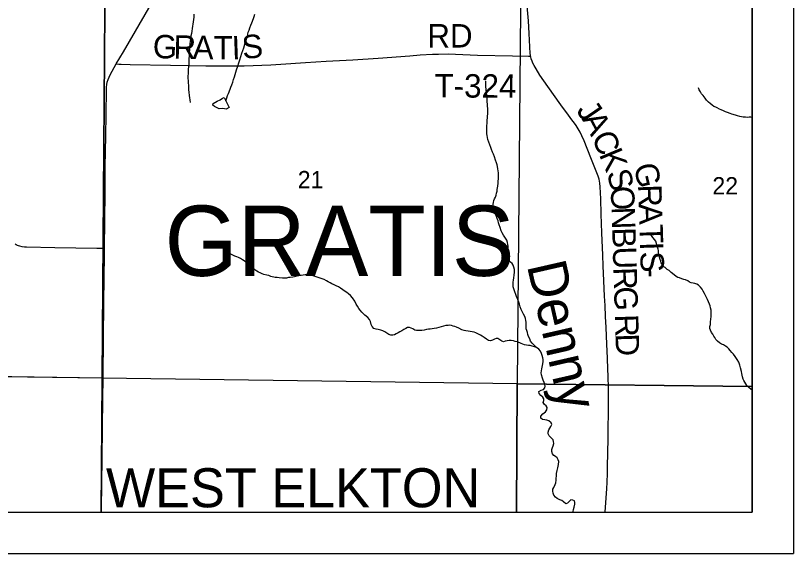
# Model space of a CAD drawing. Extents: x -8.8 to 41.4, y 0 to 34.6.
# Drawn here: x -3.661 to -1.774, y 14 to 15.304 of the extents above; entities that cross this region are included whole.
import ezdxf

# ---------------------------------------------------------------- set-up
doc = ezdxf.new("R2010")
doc.units = 0
for name, color, linetype in [('GM_X_Corporation', 7, 'Continuous'), ('GM_X_County_Road', 7, 'Continuous'), ('GM_X_Minor_River', 7, 'Continuous'), ('GM_X_Minor_River_Text', 7, 'Continuous'), ('GM_X_Section_Text', 7, 'Continuous'), ('GM_X_State_Location', 7, 'Continuous'), ('GM_X_State_Route', 7, 'Continuous'), ('GM_X_Township_Road', 7, 'Continuous'), ('GM_X_Township_Text', 7, 'Continuous'), ('GM_X_Unincorporated', 7, 'Continuous'), ('SH_Border', 7, 'Continuous')]:
    doc.layers.add(name, color=color, linetype=linetype)

msp = doc.modelspace()

# ---------------------------------------------------------------- linework, layer by layer
at = {"layer": 'GM_X_Corporation'}
msp.add_lwpolyline([(-5.4008, 18.6369), (-5.4129, 17.3836), (-5.4212, 16.5483), (-5.4282, 16.3507), (-5.435, 15.3164), (-5.4368, 15.0446), (-5.4404, 14.5882), (-5.4429, 14.2618), (-5.4432, 14.2265), (-5.4442, 14.1), (-1.8743, 14.1), (-1.8743, 18.5906)], dxfattribs=at)
for points in [[(-4.4369, 15.4422), (-3.4436, 15.4293), (-3.4507, 14.4245), (-4.4383, 14.4395)], [(-3.4436, 15.4293), (-2.4357, 15.4097), (-2.4445, 14.411), (-3.4507, 14.4245)], [(-1.8743, 14.4042), (-1.8743, 15.4006), (-2.4357, 15.4097), (-2.4445, 14.411)], [(-4.443, 14.1), (-3.4536, 14.1), (-3.4507, 14.4245), (-4.4383, 14.4395)], [(-3.9447, 14.1), (-3.4526, 14.1), (-3.4525, 14.1076), (-3.4509, 14.2324), (-3.4492, 14.3764), (-3.4488, 14.4247), (-3.938, 14.4315)], [(-3.4536, 14.1), (-2.4463, 14.1), (-2.4445, 14.411), (-3.4507, 14.4245)], [(-2.4463, 14.1), (-1.8743, 14.1), (-1.8743, 14.4042), (-2.4445, 14.411)]]:
    msp.add_lwpolyline(points, close=True, dxfattribs=at)
at = {"layer": 'GM_X_County_Road'}
msp.add_lwpolyline([(-3.4451, 14.7387), (-3.451, 14.7389), (-3.4641, 14.7393), (-3.5659, 14.741), (-3.6342, 14.742), (-3.6392, 14.7423), (-3.6446, 14.7431), (-3.6501, 14.7445), (-3.6535, 14.7456), (-3.6563, 14.7466), (-3.6592, 14.7478), (-3.6618, 14.7492)], dxfattribs=at)
at = {"layer": 'GM_X_Minor_River'}
for points in [[(-3.2282, 15.3068), (-3.2288, 15.3), (-3.2293, 15.294), (-3.2299, 15.2887), (-3.2312, 15.2826), (-3.2317, 15.2777), (-3.2326, 15.272), (-3.2336, 15.2656), (-3.2345, 15.2599), (-3.2354, 15.2542), (-3.2368, 15.2463), (-3.2373, 15.2414), (-3.2382, 15.2349), (-3.2388, 15.2266), (-3.239, 15.2201), (-3.2396, 15.2148), (-3.2403, 15.1901), (-3.2408, 15.1852), (-3.2419, 15.1739), (-3.242, 15.1685), (-3.2422, 15.1632), (-3.2427, 15.1568), (-3.2429, 15.1515), (-3.2426, 15.1461), (-3.2424, 15.14), (-3.2418, 15.1347), (-3.2414, 15.1233), (-3.2408, 15.1183), (-3.2395, 15.1103), (-3.2389, 15.1046), (-3.2383, 15.0997), (-3.2377, 15.0932)], [(-3.1509, 15.0974), (-3.1504, 15.0991), (-3.1487, 15.1043), (-3.1466, 15.1103), (-3.1446, 15.1145), (-3.1405, 15.125), (-3.1388, 15.1299), (-3.1367, 15.1359), (-3.1342, 15.1426), (-3.1322, 15.149), (-3.1297, 15.1554), (-3.125, 15.172), (-3.1221, 15.1814), (-3.1192, 15.1893), (-3.1167, 15.1968), (-3.1146, 15.2043), (-3.112, 15.2122), (-3.1095, 15.2194), (-3.1071, 15.2258), (-3.1037, 15.2378), (-3.1016, 15.2442), (-3.1003, 15.2495), (-3.0986, 15.254), (-3.0977, 15.2585), (-3.0965, 15.2634), (-3.0944, 15.2687), (-3.0927, 15.2743), (-3.0906, 15.2803), (-3.0882, 15.286), (-3.0841, 15.2965), (-3.0824, 15.3014), (-3.0803, 15.307)], [(-2.4667, 14.749), (-2.4677, 14.7536), (-2.4697, 14.759), (-2.4743, 14.7663), (-2.4775, 14.7717), (-2.4811, 14.7772), (-2.4832, 14.7822), (-2.4859, 14.7898), (-2.4879, 14.7964), (-2.4893, 14.801), (-2.4902, 14.8059), (-2.4926, 14.8121), (-2.4943, 14.8163), (-2.4975, 14.8236), (-2.4995, 14.829), (-2.5012, 14.8352), (-2.5025, 14.8413), (-2.5023, 14.8462), (-2.5018, 14.8504), (-2.5008, 14.8553), (-2.4992, 14.8594), (-2.4972, 14.8636), (-2.4955, 14.8681), (-2.4942, 14.8734), (-2.4932, 14.8783), (-2.4927, 14.8825), (-2.4913, 14.8904), (-2.4907, 14.8976), (-2.4901, 14.9025), (-2.4895, 14.9082), (-2.4894, 14.9132), (-2.4896, 14.9181), (-2.4898, 14.9223), (-2.4903, 14.9276), (-2.4909, 14.9318), (-2.4922, 14.9376), (-2.4928, 14.9418), (-2.4945, 14.9468), (-2.497, 14.9529), (-2.4993, 14.961), (-2.5017, 14.9675), (-2.5038, 14.9729), (-2.5062, 14.9794), (-2.5083, 14.9837), (-2.513, 14.9968), (-2.5151, 15.0029), (-2.5164, 15.0079), (-2.517, 15.0132), (-2.5176, 15.0174), (-2.5177, 15.0235), (-2.5176, 15.0281), (-2.5177, 15.0334), (-2.5173, 15.0459), (-2.5168, 15.0505), (-2.5162, 15.0558), (-2.516, 15.0604), (-2.5155, 15.0645), (-2.5151, 15.0748), (-2.5154, 15.079), (-2.5159, 15.0835), (-2.5165, 15.0893), (-2.5167, 15.0946), (-2.5174, 15.1072), (-2.5183, 15.1118), (-2.5185, 15.116), (-2.5197, 15.1259), (-2.5203, 15.1305), (-2.5205, 15.1354), (-2.5201, 15.1449)], [(-1.8743, 15.0568), (-1.8774, 15.0572), (-1.8815, 15.0573), (-1.8856, 15.057), (-1.8905, 15.0572), (-1.8961, 15.0577), (-1.9006, 15.0582), (-1.9047, 15.0591), (-1.9096, 15.0608), (-1.9148, 15.0621), (-1.9237, 15.0646), (-1.9278, 15.0662), (-1.9341, 15.0687), (-1.9393, 15.0707), (-1.9437, 15.0728), (-1.9496, 15.0752), (-1.9537, 15.0769), (-1.9589, 15.0797), (-1.9629, 15.0817), (-1.967, 15.0833), (-1.9718, 15.0865), (-1.9765, 15.0905), (-1.9805, 15.094), (-1.9849, 15.0987), (-1.9881, 15.1033), (-1.9931, 15.1096), (-1.9975, 15.1139), (-1.9999, 15.1185), (-2.0031, 15.1235), (-2.0048, 15.1285)], [(-3.1509, 15.0974), (-3.1428, 15.081), (-3.1501, 15.0771), (-3.158, 15.0784), (-3.1672, 15.0779), (-3.1739, 15.0812), (-3.1787, 15.0836), (-3.1825, 15.0864), (-3.1816, 15.0905), (-3.1723, 15.096), (-3.1646, 15.0991), (-3.1588, 15.1035)], [(-3.1588, 15.1035), (-3.1551, 15.1054)], [(-3.1551, 15.1054), (-3.1509, 15.0974)], [(-2.1004, 14.7248), (-2.1014, 14.7298), (-2.1017, 14.734), (-2.1027, 14.7378), (-2.1055, 14.747), (-2.1065, 14.7516), (-2.1082, 14.7566), (-2.1141, 14.7651), (-2.1177, 14.769), (-2.1214, 14.7733)], [(-2.3568, 14.2609), (-2.3555, 14.2666), (-2.3561, 14.2712), (-2.3574, 14.2754), (-2.3625, 14.2808), (-2.3668, 14.2852), (-2.3693, 14.2898), (-2.3695, 14.294), (-2.3678, 14.2993), (-2.3651, 14.3034), (-2.3626, 14.3079), (-2.3602, 14.3127), (-2.3616, 14.3169), (-2.3674, 14.3217), (-2.3722, 14.3233), (-2.3775, 14.3239), (-2.3827, 14.3248), (-2.3867, 14.3279), (-2.3873, 14.3325), (-2.3818, 14.3384), (-2.376, 14.3432), (-2.3721, 14.3481), (-2.3715, 14.3534), (-2.374, 14.358), (-2.3784, 14.3612), (-2.3809, 14.3658), (-2.3799, 14.3703), (-2.3794, 14.3745), (-2.3819, 14.3791), (-2.387, 14.3827), (-2.3906, 14.3878), (-2.3915, 14.3927), (-2.3858, 14.396), (-2.3805, 14.397), (-2.3773, 14.4011), (-2.3768, 14.4056), (-2.3774, 14.4098), (-2.3787, 14.414), (-2.3815, 14.4198), (-2.3832, 14.4248), (-2.3852, 14.4329), (-2.3858, 14.4375), (-2.3856, 14.4424), (-2.3847, 14.4473), (-2.3829, 14.4552), (-2.382, 14.4594), (-2.3814, 14.4651), (-2.3816, 14.47), (-2.3822, 14.4742), (-2.3835, 14.4796), (-2.3856, 14.4846), (-2.388, 14.49), (-2.392, 14.4947), (-2.3971, 14.4994), (-2.4029, 14.5049), (-2.4076, 14.5096), (-2.412, 14.5147), (-2.414, 14.52), (-2.4165, 14.5254), (-2.4182, 14.5304), (-2.4195, 14.5354), (-2.4208, 14.54), (-2.4225, 14.5446), (-2.4228, 14.5492), (-2.4229, 14.5545), (-2.4227, 14.5606), (-2.4233, 14.5648), (-2.4243, 14.5694), (-2.426, 14.574), (-2.4288, 14.5798), (-2.432, 14.586), (-2.4348, 14.5914), (-2.4368, 14.5975), (-2.4388, 14.6044), (-2.4405, 14.6094), (-2.4429, 14.6152), (-2.445, 14.6202), (-2.4477, 14.6279), (-2.4498, 14.634), (-2.4521, 14.6417), (-2.4539, 14.6459), (-2.4544, 14.6509), (-2.4542, 14.6577), (-2.4533, 14.6623), (-2.4523, 14.6676), (-2.4513, 14.6744), (-2.4511, 14.6816), (-2.4512, 14.6884), (-2.4521, 14.6938), (-2.4539, 14.6984), (-2.4567, 14.7027), (-2.4607, 14.7062), (-2.4651, 14.7105), (-2.4675, 14.7159), (-2.4688, 14.7205), (-2.4694, 14.7247), (-2.4689, 14.73), (-2.4672, 14.7353), (-2.4663, 14.7398), (-2.4661, 14.7448), (-2.4667, 14.749)], [(-2.8936, 14.6536), (-2.8976, 14.656), (-2.9024, 14.6581), (-2.9065, 14.6605), (-2.9124, 14.6637), (-2.922, 14.667), (-2.9295, 14.6695), (-2.9339, 14.6712), (-2.9391, 14.6728), (-2.9443, 14.6741), (-2.9488, 14.6746), (-2.9537, 14.6752), (-2.9586, 14.6749), (-2.9631, 14.6743), (-2.968, 14.6737), (-2.9737, 14.6727), (-2.9782, 14.6721), (-2.9846, 14.6707), (-2.9888, 14.6697), (-2.9949, 14.6691), (-2.999, 14.6685), (-3.0039, 14.6675), (-3.0092, 14.6672), (-3.0133, 14.6674), (-3.0219, 14.668), (-3.0264, 14.6685), (-3.0313, 14.669), (-3.0417, 14.6716), (-3.0469, 14.6737), (-3.0518, 14.6746), (-3.0585, 14.6763), (-3.0626, 14.6775), (-3.0677, 14.68), (-3.0718, 14.6816), (-3.0758, 14.6844), (-3.0802, 14.6876), (-3.0846, 14.6903), (-3.0894, 14.6943), (-3.0974, 14.7014), (-3.1021, 14.7057), (-3.1065, 14.7092), (-3.1105, 14.712), (-3.115, 14.7148), (-3.1198, 14.7172), (-3.1242, 14.7189), (-3.129, 14.7209), (-3.1342, 14.7233), (-3.1386, 14.7254), (-3.1435, 14.7266)], [(-1.8743, 14.3956), (-1.8775, 14.3978), (-1.8827, 14.4022), (-1.8871, 14.4069), (-1.8896, 14.4111), (-1.8922, 14.415), (-1.8943, 14.4188), (-1.8961, 14.4227), (-1.8979, 14.4284), (-1.8992, 14.4361), (-1.9005, 14.4407), (-1.9026, 14.4498), (-1.9043, 14.4564), (-1.9071, 14.4633), (-1.9107, 14.4702), (-1.9158, 14.4776), (-1.9195, 14.4826), (-1.9239, 14.4869), (-1.9276, 14.4916), (-1.9309, 14.4955), (-1.9353, 14.4998), (-1.939, 14.5026), (-1.9439, 14.5054), (-1.9491, 14.5074), (-1.954, 14.5106), (-1.9588, 14.5145), (-1.9624, 14.5188), (-1.965, 14.523), (-1.9675, 14.5269), (-1.9697, 14.5315), (-1.973, 14.5358), (-1.9755, 14.5408), (-1.9769, 14.5454), (-1.9767, 14.55), (-1.9758, 14.5549), (-1.9753, 14.5617), (-1.9747, 14.5678), (-1.9741, 14.5746), (-1.9737, 14.5894), (-1.9751, 14.5952), (-1.9761, 14.6001), (-1.9779, 14.604), (-1.9803, 14.6101), (-1.9825, 14.6151), (-1.9843, 14.619), (-1.9879, 14.6255), (-1.99, 14.6302), (-1.9929, 14.6359), (-1.9958, 14.6406), (-1.9998, 14.6452), (-2.0043, 14.6499), (-2.0087, 14.6527), (-2.0132, 14.6544), (-2.0178, 14.6549), (-2.0223, 14.6558), (-2.0264, 14.6578), (-2.0305, 14.6605), (-2.0358, 14.663), (-2.0403, 14.6642), (-2.0452, 14.6655), (-2.0504, 14.6676), (-2.0549, 14.6688), (-2.0587, 14.6712), (-2.0639, 14.6752), (-2.0709, 14.6811), (-2.0761, 14.6854), (-2.0809, 14.6882), (-2.0857, 14.6933), (-2.0899, 14.6953), (-2.0916, 14.6991), (-2.0953, 14.7042), (-2.0963, 14.7084), (-2.0977, 14.7126), (-2.0997, 14.721), (-2.1004, 14.7248)], [(-2.3971, 14.4994), (-2.4127, 14.504), (-2.4172, 14.5038), (-2.4217, 14.5047), (-2.4262, 14.5059), (-2.4306, 14.5076), (-2.4347, 14.5092), (-2.4436, 14.5125), (-2.4488, 14.5138), (-2.4529, 14.5151), (-2.4585, 14.516), (-2.4634, 14.5161), (-2.4683, 14.5155), (-2.4732, 14.5141), (-2.4778, 14.5131), (-2.4819, 14.5144), (-2.4863, 14.5175), (-2.491, 14.5207), (-2.4955, 14.5209), (-2.4997, 14.5195), (-2.5043, 14.5173), (-2.5093, 14.5155), (-2.5137, 14.5164), (-2.5189, 14.5196), (-2.5247, 14.5236), (-2.5291, 14.5268), (-2.5336, 14.5288), (-2.5395, 14.5324), (-2.5443, 14.5348), (-2.5483, 14.5361), (-2.5536, 14.5374), (-2.558, 14.5383), (-2.5629, 14.5384), (-2.5685, 14.5393), (-2.5726, 14.5402), (-2.5786, 14.5423), (-2.5856, 14.5459), (-2.5911, 14.5483), (-2.5952, 14.55), (-2.5997, 14.5512), (-2.6037, 14.5525), (-2.6079, 14.553), (-2.612, 14.5527), (-2.6173, 14.5521), (-2.623, 14.5508), (-2.629, 14.549), (-2.6347, 14.5477), (-2.64, 14.5463), (-2.6457, 14.545), (-2.6552, 14.5437), (-2.6597, 14.5435), (-2.6646, 14.5428), (-2.6699, 14.5415), (-2.6759, 14.5405), (-2.6808, 14.5403), (-2.6884, 14.5401), (-2.6928, 14.5414), (-2.6976, 14.5442), (-2.7017, 14.5462), (-2.7057, 14.5478), (-2.7103, 14.5476), (-2.7145, 14.545), (-2.7195, 14.5425), (-2.7244, 14.5396), (-2.7287, 14.5371), (-2.7329, 14.5349), (-2.7375, 14.532), (-2.7417, 14.5302), (-2.7462, 14.5292), (-2.7507, 14.5294), (-2.7556, 14.5306), (-2.7603, 14.5338), (-2.7655, 14.5374), (-2.7703, 14.5398), (-2.7751, 14.5411), (-2.7818, 14.5428), (-2.7863, 14.5437), (-2.7919, 14.545), (-2.7962, 14.5501), (-2.7987, 14.5551), (-2.8003, 14.562), (-2.8024, 14.567), (-2.8067, 14.572), (-2.814, 14.5776), (-2.8213, 14.5846), (-2.8249, 14.5897), (-2.8285, 14.594), (-2.8313, 14.599), (-2.8348, 14.6044), (-2.838, 14.6114), (-2.8437, 14.6199), (-2.8488, 14.6254), (-2.8531, 14.6293), (-2.8575, 14.6328), (-2.8615, 14.6352), (-2.8671, 14.6388), (-2.8725, 14.6432), (-2.8777, 14.646), (-2.8832, 14.6484), (-2.8884, 14.6508), (-2.8936, 14.6536)], [(-2.3086, 14.1), (-2.3084, 14.1013), (-2.3075, 14.1062), (-2.3061, 14.1123), (-2.3048, 14.1191), (-2.3042, 14.1236), (-2.3052, 14.1278), (-2.3097, 14.1291), (-2.3138, 14.13), (-2.3184, 14.1259), (-2.322, 14.1215), (-2.3262, 14.1201), (-2.3316, 14.1252), (-2.336, 14.1279), (-2.3412, 14.1296), (-2.3471, 14.1328), (-2.3511, 14.136), (-2.3551, 14.1414), (-2.3568, 14.1457), (-2.3581, 14.1506), (-2.3576, 14.1556), (-2.3555, 14.1597), (-2.3523, 14.1668), (-2.3506, 14.1713), (-2.3497, 14.1774), (-2.3495, 14.1816), (-2.3493, 14.188), (-2.3487, 14.1941), (-2.3473, 14.2009), (-2.3459, 14.2073), (-2.3441, 14.2157), (-2.3435, 14.2225), (-2.3445, 14.2271), (-2.347, 14.2313), (-2.351, 14.2353), (-2.3558, 14.2373), (-2.359, 14.2416), (-2.3603, 14.2469), (-2.3601, 14.2515), (-2.3585, 14.2568), (-2.3568, 14.2609)]]:
    msp.add_lwpolyline(points, dxfattribs=at)
at = {"layer": 'GM_X_State_Route'}
msp.add_line((-3.4486, 14.4242), (-3.4485, 14.4302), dxfattribs=at)
for points in [[(-3.4485, 14.4302), (-3.4464, 14.6094), (-3.4452, 14.7243), (-3.4451, 14.7387), (-3.4439, 14.8746), (-3.4433, 14.9367), (-3.4422, 15.0125), (-3.4415, 15.0641), (-3.4407, 15.1237), (-3.4403, 15.1305), (-3.4395, 15.1365), (-3.4383, 15.1423), (-3.4364, 15.1484), (-3.4339, 15.1543), (-3.4312, 15.1598), (-3.4264, 15.1686), (-3.4165, 15.1864), (-3.399, 15.216), (-3.332, 15.3315)], [(-3.4523, 14.1), (-3.4522, 14.1071), (-3.4507, 14.2318), (-3.449, 14.3758), (-3.4486, 14.4242)]]:
    msp.add_lwpolyline(points, dxfattribs=at)
at = {"layer": 'GM_X_Township_Road'}
for points in [[(-2.2307, 14.1), (-2.2307, 14.1006), (-2.2266, 14.1569), (-2.2258, 14.173), (-2.2252, 14.1935), (-2.225, 14.2109), (-2.2238, 14.278), (-2.2236, 14.3016), (-2.2232, 14.3426), (-2.2228, 14.4003), (-2.2238, 14.4295), (-2.2245, 14.4469), (-2.2254, 14.4729), (-2.2268, 14.5071), (-2.2287, 14.548), (-2.23, 14.574), (-2.2312, 14.6007), (-2.2322, 14.6237), (-2.2342, 14.6608), (-2.2358, 14.6974), (-2.2367, 14.7228), (-2.2386, 14.7768), (-2.2403, 14.8221), (-2.2416, 14.8594), (-2.2422, 14.8737), (-2.243, 14.8886), (-2.2438, 14.8972), (-2.2446, 14.9021), (-2.2456, 14.907), (-2.2479, 14.9147), (-2.2655, 14.9592), (-2.2821, 15.0001), (-2.2872, 15.012), (-2.2917, 15.0209), (-2.2964, 15.0291), (-2.3013, 15.0369), (-2.3052, 15.0425), (-2.3114, 15.051), (-2.3195, 15.062), (-2.3382, 15.0875), (-2.3703, 15.1318), (-2.3891, 15.1595), (-2.3984, 15.1742), (-2.4032, 15.1829), (-2.406, 15.1884), (-2.4082, 15.1935), (-2.4101, 15.1988), (-2.4115, 15.2036), (-2.4117, 15.2051), (-2.4122, 15.2078), (-2.4127, 15.2115), (-2.4152, 15.2599), (-2.4171, 15.2908), (-2.4218, 15.3458)], [(-3.4165, 15.1864), (-3.4107, 15.186), (-3.4051, 15.1855), (-3.3828, 15.185), (-3.2853, 15.1835), (-3.199, 15.182), (-3.1642, 15.182), (-3.1065, 15.1818), (-3.042, 15.1842), (-3.0173, 15.1855), (-2.9576, 15.1901), (-2.9075, 15.1929), (-2.843, 15.1967), (-2.7816, 15.2007), (-2.7048, 15.2062), (-2.6794, 15.2085), (-2.65, 15.2101), (-2.6353, 15.2101), (-2.612, 15.2106), (-2.5407, 15.208), (-2.4558, 15.2062), (-2.4169, 15.2052), (-2.4117, 15.2051)]]:
    msp.add_lwpolyline(points, dxfattribs=at)
at = {"layer": 'SH_Border'}
for p, q in [((-1.7743, 21), (-1.7743, 14)), ((-1.8743, 20.9), (-1.8743, 14.1)), ((-8.6743, 14.1), (-1.8743, 14.1)), ((-8.7743, 14), (-1.7743, 14))]:
    msp.add_line(p, q, dxfattribs=at)

# ---------------------------------------------------------------- texts
at = {"layer": 'GM_X_Minor_River_Text'}
msp.add_text('Denny', height=0.09467, rotation=282.8389, dxfattribs=at).set_placement((-2.4211, 14.6982))
at = {"layer": 'GM_X_Section_Text'}
for s, height, rotation, p in [('RD', 0.05682, 0, (-2.6622, 15.2263)), ('G', 0.0568, 358.8306, (-3.3284, 15.2005)), ('R', 0.0568, 358.829, (-3.2784, 15.1994)), ('A', 0.0568, 358.8364, (-3.2317, 15.1985)), ('T', 0.0568, 359.7279, (-3.1808, 15.1975)), ('I', 0.0568, 2.1244, (-3.1357, 15.1973)), ('S', 0.0568, 4.9908, (-3.1093, 15.1984)), ('T-324', 0.05682, 359.7186, (-2.6448, 15.1053)), ('J', 0.0568, 304.4157, (-2.3024, 15.0733)), ('A', 0.0568, 298.4462, (-2.2881, 15.0527)), ('C', 0.0568, 293.1786, (-2.2649, 15.01)), ('K', 0.0568, 292.6538, (-2.2466, 14.9672)), ('G', 0.0568, 283.409, (-2.1623, 14.9392)), ('S', 0.0568, 286.1565, (-2.2279, 14.9226)), ('O', 0.0568, 272.4943, (-2.2178, 14.8894)), ('R', 0.0568, 271.8367, (-2.1512, 14.8936)), ('N', 0.0568, 271.8089, (-2.2156, 14.8396)), ('A', 0.0568, 271.8089, (-2.1497, 14.847)), ('T', 0.0568, 271.811, (-2.1481, 14.797)), ('B', 0.0568, 271.7683, (-2.2141, 14.7896)), ('U', 0.0568, 271.7689, (-2.2126, 14.743)), ('I', 0.0568, 271.8073, (-2.1467, 14.7545)), ('S', 0.0568, 271.8099, (-2.146, 14.7312)), ('R', 0.0568, 271.7702, (-2.2111, 14.693)), ('-', 0.0568, 271.8132, (-2.1448, 14.6929)), ('G', 0.0568, 271.7689, (-2.2096, 14.6463)), ('R', 0.0568, 271.7692, (-2.2075, 14.5789)), ('D', 0.0568, 271.7693, (-2.2061, 14.5322))]:
    msp.add_text(s, height=height, rotation=rotation, dxfattribs=at).set_placement(p)
at = {"layer": 'GM_X_State_Location'}
msp.add_text('GRATIS', height=0.17045, rotation=0, dxfattribs=at).set_placement((-3.2993, 14.6727))
at = {"layer": 'GM_X_Township_Text'}
for s, p in [('21', (-2.9764, 14.8852)), ('22', (-1.9709, 14.8702))]:
    msp.add_text(s, height=0.04186, rotation=0, dxfattribs=at).set_placement(p)
at = {"layer": 'GM_X_Unincorporated'}
msp.add_text('WEST ELKTON', height=0.094697, rotation=0, dxfattribs=at).set_placement((-3.4417, 14.1118))

doc.saveas('drawing.dxf')
